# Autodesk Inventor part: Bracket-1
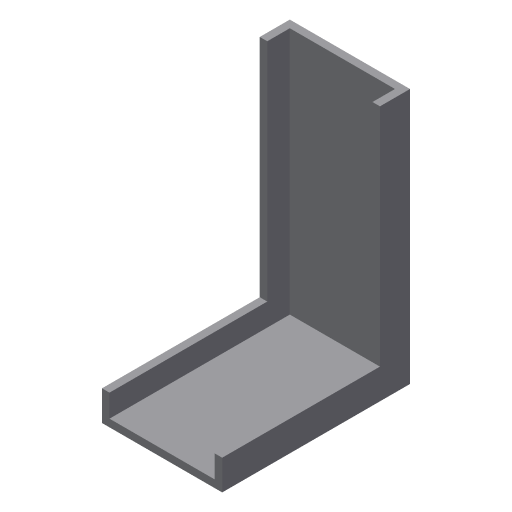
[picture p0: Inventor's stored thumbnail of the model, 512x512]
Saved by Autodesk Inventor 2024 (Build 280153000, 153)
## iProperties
Shininess: 77.0
Length Units: 11269
Angle Units: 11279
Time Units: 11290
Mass Units: 11283
Length Display Precision: 3
Angle Display Precision: 2
Created: 2002-04
Part Number: Bracket-1
Document SubType Name: Modeling
Density: 1 g/cm^3
Material: Generic
Appearance: Default
Density: 0.0
Volumn: 0.0
Area: 0.0
PropertySet Name: Model Information
Control State: 0
Master: False
Checked Out: False
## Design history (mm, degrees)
sketch "Sketch2"
  geometry: L1 (-4.258, 23.699)-(-4.258, -18.801); L2 (-4.258, -18.801)-(26.992, -18.801); L3 (26.992, -18.801)-(26.992, -13.801); L4 (26.992, -13.801)-(0.742, -13.801); L5 (0.742, -13.801)-(0.742, 23.699); L6 (0.742, 23.699)-(-4.258, 23.699)
  constraints: 12 end point, 4 parallel, 2 perpendicular, 1 vertical
  dimensions: "d0" = 31.25 distance of L1.end L2.end; "d1" = 42.5 distance of L1.start L1.end; "d2" = 5 distance of L2.end L3.end
extrude "Extrusion1" new body sketch "Sketch2" stored distance "d3" = 20; taper "d4" = 0 deg
shell "Shell1" dims "d5" = 1.25
body "Solid1"
node "Sketch1"
